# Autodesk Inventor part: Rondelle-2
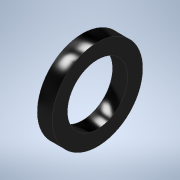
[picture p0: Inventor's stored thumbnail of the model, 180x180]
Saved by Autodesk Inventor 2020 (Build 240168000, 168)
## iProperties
Created: 2023-10
Part Number: Rondelle-2
Material: Générique
Document SubType Name: Modeling
Designer: bruno
Density: 1 g/cm^3
Appearance: Noir
Author: bruno
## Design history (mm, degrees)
sketch "Esquisse1"
  geometry: C1 r 3 at (0, 0); C2 r 2 at (0, 0); 1 further point
  constraints: 2 centre point, 2 coincident
  dimensions: "d0" = 6 diameter of C1; "d1" = 4 diameter of C2
extrude "Extrusion1" new body sketch "Esquisse1" distance "d2" = 1; taper "d3" = 0 deg
node "Solide1"
